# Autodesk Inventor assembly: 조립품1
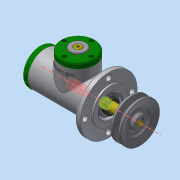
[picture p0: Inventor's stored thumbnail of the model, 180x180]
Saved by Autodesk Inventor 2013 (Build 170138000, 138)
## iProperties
Created: 2016-08
Part Number: 조립품1
Document SubType Name: Assembly
Designer: Administrator
Author: Administrator
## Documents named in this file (21)
- C:\Users\Administrator\Desktop\460807V1017\조립품1.iam
- C:\Users\Administrator\Desktop\460807V1017\1-본체.ipt
- C:\Users\Administrator\Desktop\460807V1017\탑 커버.ipt
- 탑 커버.ipt
- C:\Users\Administrator\Desktop\460807V1017\탑 부시.ipt
- C:\Users\Administrator\Desktop\460807V1017\사이드 커버.ipt
- 사이드 커버.ipt
- C:\Users\Administrator\Desktop\460807V1017\편심축.ipt
- C:\Users\Administrator\Desktop\460807V1017\베어링 15 x 35 x 11.ipt
- C:\Users\Administrator\Desktop\460807V1017\멈춤링 15 x 1.ipt
- C:\Users\Administrator\Desktop\460807V1017\부시1.ipt
- C:\Users\Administrator\Desktop\460807V1017\멈춤링 35x1.6.ipt
- C:\Users\Administrator\Desktop\460807V1017\부시2.ipt
- C:\Users\Administrator\Desktop\460807V1017\와셔 10x21.ipt
- C:\Users\Administrator\Desktop\460807V1017\너트 M10.ipt
- C:\Users\Administrator\Desktop\460807V1017\슬라이더.ipt
- C:\Users\Administrator\Desktop\460807V1017\링크.ipt
- C:\Users\Administrator\Desktop\460807V1017\클래스터 핀 6 x 24.ipt
- C:\Users\Administrator\Desktop\460807V1017\오일 실 15 25 7.ipt
- C:\Users\Administrator\Desktop\460807V1017\키 4 x 4 x 18.ipt
- C:\Users\Administrator\Desktop\460807V1017\V-벨트풀리.ipt
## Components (2 placed, 2 different names)
1. 1-본체:1
2. V-벨트풀리:1 — 각도:2
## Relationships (1: Angle 1)
- 각도:2 [Angle]: V-벨트풀리:1
